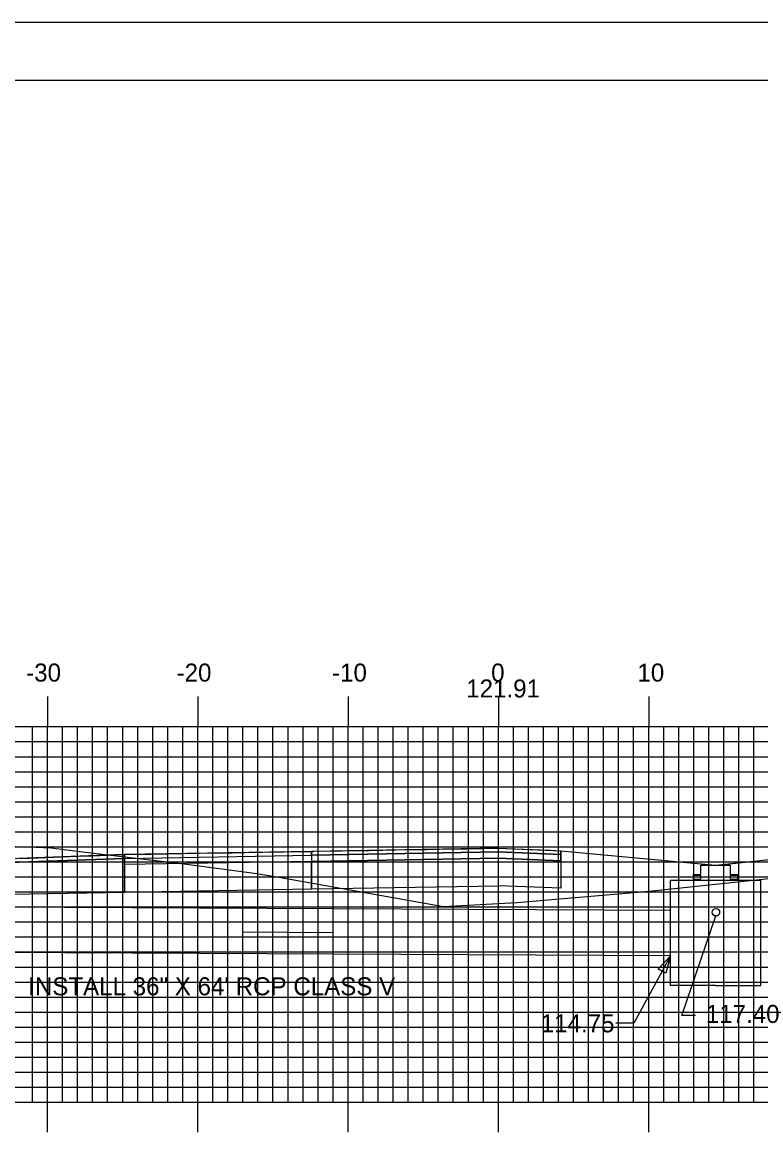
# Model space of a CAD drawing. Extents: x 853894 to 854237, y 366605 to 366825.
# Drawn here: x 854027.9 to 854077, y 366750.6 to 366824.9 of the extents above; entities that cross this region are included whole.
import ezdxf

# ---------------------------------------------------------------- set-up
doc = ezdxf.new("R2010")
doc.units = 0
for name, color, linetype in [('ANNOTATION', 7, 'Continuous'), ('BORDER', 7, 'Continuous'), ('D_Drainage_CB_TypeA1-B1', 7, 'Continuous'), ('D_Drainage_Culvert', 7, 'Continuous'), ('D_Drainage_Text', 7, 'Continuous'), ('D_Roadway_Centerline', 7, 'Continuous'), ('D_Roadway_Centerline_Text', 7, 'Continuous'), ('D_Roadway_Edge_Shoulder', 7, 'Continuous'), ('D_Roadway_Edge_TW', 7, 'Continuous'), ('D_Roadway_Pavement', 7, 'Continuous'), ('D_Roadway_SubGrade', 7, 'Continuous'), ('D_Text_Standard', 7, 'Continuous'), ('H_V ANNOTATION', 7, 'Continuous'), ('MAJOR', 7, 'Continuous'), ('MINOR', 7, 'Continuous'), ('PLOT BOUNDARY', 7, 'Continuous'), ('S_Roadway_Centerline', 7, 'Continuous')]:
    doc.layers.add(name, color=color, linetype=linetype)

msp = doc.modelspace()

# ---------------------------------------------------------------- linework, layer by layer
at = {"layer": 'ANNOTATION'}
msp.add_lwpolyline([(854072.65, 366758.819), (854071.729, 366758.819), (854074.001, 366765.451)], dxfattribs=at)
at = {"layer": 'BORDER'}
msp.add_lwpolyline([(853909.93, 366611.055), (854229.93, 366611.055), (854229.93, 366821.055), (853909.93, 366821.055)], close=True, dxfattribs=at)
at = {"layer": 'D_Drainage_CB_TypeA1-B1'}
msp.add_line((854070.983, 366767.828), (854076.977, 366767.828), dxfattribs=at)
for points in [[(854072.467, 366768.204), (854072.992, 366768.204), (854072.992, 366768.828), (854074.961, 366768.828), (854074.961, 366768.204), (854075.486, 366768.204)], [(854073.977, 366760.828), (854070.983, 366760.828), (854070.983, 366767.828)], [(854073.977, 366760.828), (854076.983, 366760.828), (854076.983, 366767.828)]]:
    msp.add_lwpolyline(points, dxfattribs=at)
for points in [[(854072.492, 366768.141), (854072.492, 366767.891), (854072.992, 366767.891), (854072.992, 366768.141)], [(854074.961, 366768.141), (854074.961, 366767.891), (854075.461, 366767.891), (854075.461, 366768.141)]]:
    msp.add_lwpolyline(points, close=True, dxfattribs=at)
at = {"layer": 'D_Drainage_Culvert'}
for p, q in [((854070.983, 366765.807), (854006.992, 366766.127)), ((854042.512, 366764.406), (854048.554, 366764.352)), ((854070.977, 366762.807), (854005.961, 366763.132))]:
    msp.add_line(p, q, dxfattribs=at)
msp.add_circle((854074.001, 366765.701), 0.25, dxfattribs=at)
at = {"layer": 'D_Roadway_Centerline'}
for points in [[(854027.695, 366769.285), (854028.309, 366769.307), (854029.951, 366769.367), (854032.09, 366769.445), (854032.202, 366769.449), (854032.472, 366769.458), (854034.644, 366769.538), (854035.872, 366769.559), (854036.408, 366769.568), (854039.651, 366769.624), (854041.834, 366769.661), (854043.429, 366769.689), (854043.828, 366769.696), (854044.953, 366769.715), (854045.281, 366769.721), (854047.087, 366769.752), (854047.192, 366769.753), (854047.211, 366769.754), (854047.265, 366769.755), (854050.989, 366769.819), (854052.695, 366769.848), (854054.773, 366769.884), (854055.611, 366769.898), (854057.437, 366769.929), (854058.455, 366769.947), (854058.552, 366769.948), (854059.53, 366769.965), (854062.331, 366769.851), (854062.974, 366769.825), (854063.677, 366769.796), (854066.111, 366769.568), (854067.515, 366769.437), (854069.891, 366769.214), (854069.907, 366769.212), (854069.918, 366769.212), (854073.497, 366768.876), (854073.673, 366768.859), (854073.977, 366768.831)], [(854063.676, 366769.797), (854073.977, 366768.828), (854083.066, 366769.781)], [(854063.677, 366769.796), (854073.977, 366768.831)], [(854073.977, 366768.831), (854074.613, 366768.898), (854074.733, 366768.91), (854077.515, 366769.2), (854079.273, 366769.384), (854080.54, 366769.516), (854083.066, 366769.78)]]:
    msp.add_lwpolyline(points, dxfattribs=at)
at = {"layer": 'D_Roadway_Edge_Shoulder'}
for points in [[(854034.644, 366769.538), (854026.348, 366769.235), (854026.348, 366768.985), (854034.644, 366769.288)], [(854059.53, 366769.965), (854063.677, 366769.796), (854063.677, 366769.546), (854059.53, 366769.715)], [(854059.53, 366769.965), (854063.676, 366769.797), (854063.676, 366769.547), (854059.53, 366769.715)]]:
    msp.add_lwpolyline(points, close=True, dxfattribs=at)
at = {"layer": 'D_Roadway_Edge_TW'}
for points in [[(854047.087, 366769.752), (854034.644, 366769.538), (854034.644, 366769.288), (854047.087, 366769.502)], [(854059.53, 366769.965), (854047.087, 366769.752), (854047.087, 366769.502), (854059.53, 366769.715)], [(854059.53, 366769.965), (854047.09, 366769.749), (854047.09, 366769.499), (854059.53, 366769.715)]]:
    msp.add_lwpolyline(points, close=True, dxfattribs=at)
at = {"layer": 'D_Roadway_Pavement'}
for points in [[(854059.53, 366769.715), (854047.087, 366769.502), (854047.087, 366769.085), (854059.53, 366769.298)], [(854059.53, 366769.715), (854063.677, 366769.546), (854063.677, 366769.129), (854059.53, 366769.298)], [(854034.644, 366769.288), (854034.644, 366768.871), (854034.644, 366768.871)]]:
    msp.add_lwpolyline(points, close=True, dxfattribs=at)
msp.add_lwpolyline([(854047.087, 366769.502), (854047.087, 366769.085)], dxfattribs=at)
at = {"layer": 'D_Roadway_SubGrade'}
for points in [[(854059.53, 366769.298), (854063.677, 366769.129), (854063.677, 366769.546), (854063.677, 366769.796), (854063.677, 366767.296), (854059.53, 366767.465)], [(854034.644, 366768.871), (854034.644, 366768.871), (854034.644, 366769.288), (854026.348, 366768.985), (854026.348, 366769.235), (854015.677, 366766.886), (854015.677, 366766.712), (854034.644, 366767.038)], [(854047.087, 366769.085), (854034.644, 366768.871), (854034.644, 366767.038), (854047.087, 366767.252)], [(854059.53, 366769.298), (854047.087, 366769.085), (854047.087, 366767.252), (854059.53, 366767.465)]]:
    msp.add_lwpolyline(points, close=True, dxfattribs=at)
at = {"layer": 'D_Text_Standard'}
msp.add_lwpolyline([(854070.977, 366762.807), (854068.544, 366758.307), (854067.348, 366758.307)], dxfattribs=at)
msp.add_lwpolyline([(854070.977, 366762.807), (854070.679, 366761.644), (854070.167, 366761.921)], close=True, dxfattribs=at)
at = {"layer": 'MAJOR'}
for p, q in [((854029.53, 366780.059), (854029.53, 366778.055)), ((854039.53, 366780.059), (854039.53, 366778.055)), ((854049.53, 366780.059), (854049.53, 366778.055)), ((854059.53, 366780.059), (854059.53, 366778.055)), ((854069.53, 366780.059), (854069.53, 366778.055)), ((853919.53, 366778.055), (854199.53, 366778.055)), ((853919.53, 366778.055), (854199.53, 366778.055)), ((854029.53, 366753.055), (854029.53, 366778.055)), ((854039.53, 366753.055), (854039.53, 366778.055)), ((854049.53, 366753.055), (854049.53, 366778.055)), ((854059.53, 366753.055), (854059.53, 366778.055)), ((854069.53, 366753.055), (854069.53, 366778.055)), ((853919.53, 366773.055), (854199.53, 366773.055)), ((853919.53, 366768.055), (854199.53, 366768.055)), ((853919.53, 366763.055), (854199.53, 366763.055)), ((853919.53, 366758.055), (854199.53, 366758.055)), ((853919.53, 366753.055), (854199.53, 366753.055)), ((853919.53, 366753.055), (854199.53, 366753.055)), ((854029.53, 366751.051), (854029.53, 366753.055)), ((854039.53, 366751.051), (854039.53, 366753.055)), ((854049.53, 366751.051), (854049.53, 366753.055)), ((854059.53, 366751.051), (854059.53, 366753.055)), ((854069.53, 366751.051), (854069.53, 366753.055))]:
    msp.add_line(p, q, dxfattribs=at)
at = {"layer": 'MINOR'}
for p, q in [((854028.53, 366753.055), (854028.53, 366778.055)), ((854030.53, 366753.055), (854030.53, 366778.055)), ((854031.53, 366753.055), (854031.53, 366778.055)), ((854032.53, 366753.055), (854032.53, 366778.055)), ((854033.53, 366753.055), (854033.53, 366778.055)), ((854034.53, 366753.055), (854034.53, 366778.055)), ((854035.53, 366753.055), (854035.53, 366778.055)), ((854036.53, 366753.055), (854036.53, 366778.055)), ((854037.53, 366753.055), (854037.53, 366778.055)), ((854038.53, 366753.055), (854038.53, 366778.055)), ((854040.53, 366753.055), (854040.53, 366778.055)), ((854041.53, 366753.055), (854041.53, 366778.055)), ((854042.53, 366753.055), (854042.53, 366778.055)), ((854043.53, 366753.055), (854043.53, 366778.055)), ((854044.53, 366753.055), (854044.53, 366778.055)), ((854045.53, 366753.055), (854045.53, 366778.055)), ((854046.53, 366753.055), (854046.53, 366778.055)), ((854047.53, 366753.055), (854047.53, 366778.055)), ((854048.53, 366753.055), (854048.53, 366778.055)), ((854050.53, 366753.055), (854050.53, 366778.055)), ((854051.53, 366753.055), (854051.53, 366778.055)), ((854052.53, 366753.055), (854052.53, 366778.055)), ((854053.53, 366753.055), (854053.53, 366778.055)), ((854054.53, 366753.055), (854054.53, 366778.055)), ((854055.53, 366753.055), (854055.53, 366778.055)), ((854056.53, 366753.055), (854056.53, 366778.055)), ((854057.53, 366753.055), (854057.53, 366778.055)), ((854058.53, 366753.055), (854058.53, 366778.055)), ((854060.53, 366753.055), (854060.53, 366778.055)), ((854061.53, 366753.055), (854061.53, 366778.055)), ((854062.53, 366753.055), (854062.53, 366778.055)), ((854063.53, 366753.055), (854063.53, 366778.055)), ((854064.53, 366753.055), (854064.53, 366778.055)), ((854065.53, 366753.055), (854065.53, 366778.055)), ((854066.53, 366753.055), (854066.53, 366778.055)), ((854067.53, 366753.055), (854067.53, 366778.055)), ((854068.53, 366753.055), (854068.53, 366778.055)), ((854070.53, 366753.055), (854070.53, 366778.055)), ((854071.53, 366753.055), (854071.53, 366778.055)), ((854072.53, 366753.055), (854072.53, 366778.055)), ((854073.53, 366753.055), (854073.53, 366778.055)), ((854074.53, 366753.055), (854074.53, 366778.055)), ((854075.53, 366753.055), (854075.53, 366778.055)), ((854076.53, 366753.055), (854076.53, 366778.055)), ((853919.53, 366777.055), (854199.53, 366777.055)), ((853919.53, 366776.055), (854199.53, 366776.055)), ((853919.53, 366775.055), (854199.53, 366775.055)), ((853919.53, 366774.055), (854199.53, 366774.055)), ((853919.53, 366772.055), (854199.53, 366772.055)), ((853919.53, 366771.055), (854199.53, 366771.055)), ((853919.53, 366770.055), (854199.53, 366770.055)), ((853919.53, 366769.055), (854199.53, 366769.055)), ((853919.53, 366767.055), (854199.53, 366767.055)), ((853919.53, 366766.055), (854199.53, 366766.055)), ((853919.53, 366765.055), (854199.53, 366765.055)), ((853919.53, 366764.055), (854199.53, 366764.055)), ((853919.53, 366762.055), (854199.53, 366762.055)), ((853919.53, 366761.055), (854199.53, 366761.055)), ((853919.53, 366760.055), (854199.53, 366760.055)), ((853919.53, 366759.055), (854199.53, 366759.055)), ((853919.53, 366757.055), (854199.53, 366757.055)), ((853919.53, 366756.055), (854199.53, 366756.055)), ((853919.53, 366755.055), (854199.53, 366755.055)), ((853919.53, 366754.055), (854199.53, 366754.055))]:
    msp.add_line(p, q, dxfattribs=at)
at = {"layer": 'PLOT BOUNDARY'}
msp.add_lwpolyline([(853893.743, 366604.937), (854233.743, 366604.937), (854233.743, 366824.937), (853893.743, 366824.937)], close=True, dxfattribs=at)
at = {"layer": 'S_Roadway_Centerline'}
msp.add_lwpolyline([(853981.12, 366770.875), (853988.126, 366769.971), (853990.615, 366769.628), (853992.708, 366769.716), (854000.923, 366770.099), (854007.583, 366770.37), (854009.896, 366770.414), (854013.492, 366770.544), (854013.643, 366770.496), (854017.799, 366770.405), (854019.41, 366770.38), (854021.357, 366770.276), (854028.746, 366770.027), (854029.778, 366769.978), (854031.855, 366769.731), (854038.786, 366768.904), (854043.458, 366768.274), (854045.051, 366768.008), (854055.871, 366766.075), (854055.885, 366766.078), (854060.762, 366766.354), (854069.555, 366767.11), (854083.433, 366768.567)], dxfattribs=at)

# ---------------------------------------------------------------- texts
at = {"layer": 'D_Drainage_Text'}
msp.add_text('INSTALL 36" X 64\' RCP CLASS V', height=1.2, dxfattribs=at).set_placement((854028.24, 366760.171))
at = {"layer": 'D_Roadway_Centerline_Text'}
msp.add_text('121.91', height=1.2, dxfattribs=at).set_placement((854057.39, 366779.995))
at = {"layer": 'D_Text_Standard'}
for s, p in [('117.40', (854073.33, 366758.33)), ('114.75', (854062.347, 366757.707))]:
    msp.add_text(s, height=1.2, dxfattribs=at).set_placement(p)
at = {"layer": 'H_V ANNOTATION'}
for s, p in [('-30', (854028.106, 366781.055)), ('-20', (854038.117, 366781.055)), ('-10', (854048.46, 366781.055)), ('0', (854059.048, 366781.055)), ('10', (854068.781, 366781.055))]:
    msp.add_text(s, height=1.2, dxfattribs=at).set_placement(p)

doc.saveas('drawing.dxf')
